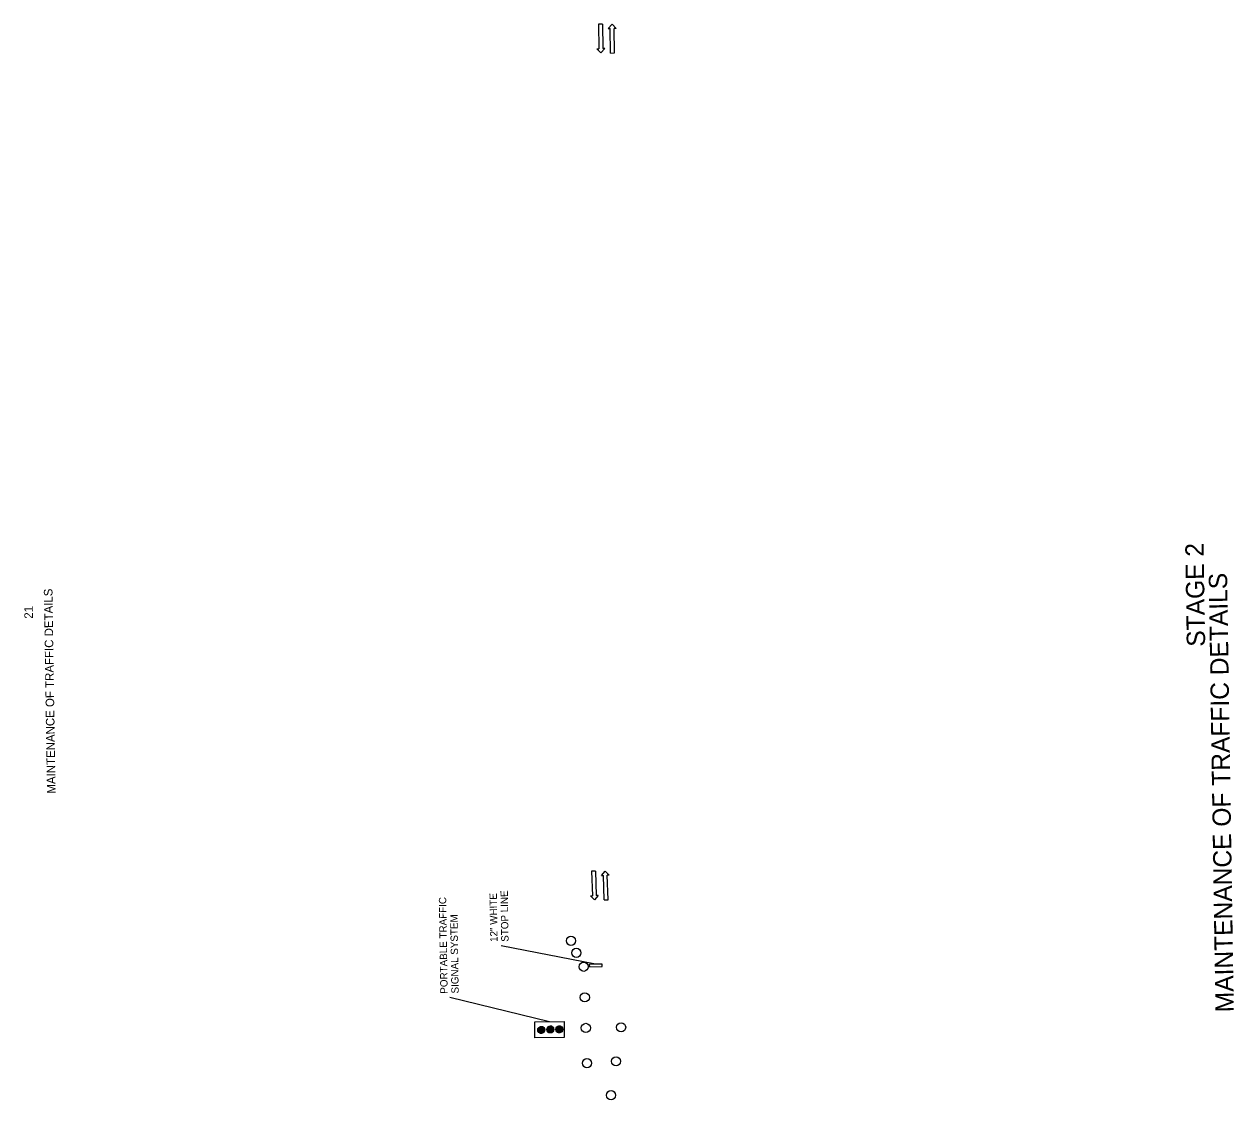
# Model space of a CAD drawing. Extents: x 1770139 to 1773492, y 718230 to 727190.
# Drawn here: x 1770334 to 1771322, y 725184 to 726062 of the extents above; entities that cross this region are included whole.
import ezdxf

# ---------------------------------------------------------------- set-up
doc = ezdxf.new("R2010")
doc.units = 0
for name, color, linetype in [('Default', 7, 'Continuous'), ('R_Border', 7, 'Continuous'), ('R_Border Notes', 7, 'Continuous'), ('R_Dimension', 7, 'Continuous'), ('R_MOT', 7, 'Continuous')]:
    doc.layers.add(name, color=color, linetype=linetype)

msp = doc.modelspace()

# ---------------------------------------------------------------- linework, layer by layer
at = {"layer": 'Default'}
for p, q in [((1770795.47, 725294.29), (1770795.54, 725292.29)), ((1770795.54, 725292.29), (1770806.07, 725292.65)), ((1770806.07, 725292.65), (1770806.01, 725294.64)), ((1770756.38, 725237.94), (1770753.33, 725240.9)), ((1770756.21, 725237.94), (1770753.33, 725240.73)), ((1770756.55, 725237.96), (1770753.34, 725241.06)), ((1770756.02, 725237.94), (1770753.35, 725240.54)), ((1770756.7, 725237.98), (1770753.36, 725241.22)), ((1770755.82, 725237.96), (1770753.37, 725240.34)), ((1770756.85, 725238.01), (1770753.39, 725241.37)), ((1770756.99, 725238.05), (1770753.42, 725241.51)), ((1770755.61, 725238), (1770753.42, 725240.12)), ((1770757.13, 725238.09), (1770753.46, 725241.65)), ((1770755.36, 725238.06), (1770753.49, 725239.88)), ((1770757.26, 725238.14), (1770753.5, 725241.78)), ((1770757.39, 725238.19), (1770753.55, 725241.91)), ((1770757.51, 725238.25), (1770753.6, 725242.03)), ((1770757.62, 725238.31), (1770753.66, 725242.15)), ((1770757.73, 725238.38), (1770753.73, 725242.26)), ((1770757.84, 725238.45), (1770753.79, 725242.37)), ((1770757.94, 725238.52), (1770753.86, 725242.48)), ((1770758.04, 725238.6), (1770753.94, 725242.58)), ((1770758.14, 725238.68), (1770754.02, 725242.67)), ((1770758.23, 725238.77), (1770754.1, 725242.77)), ((1770758.31, 725238.86), (1770754.19, 725242.86)), ((1770758.4, 725238.95), (1770754.28, 725242.94)), ((1770758.48, 725239.05), (1770754.37, 725243.03)), ((1770758.55, 725239.15), (1770754.47, 725243.1)), ((1770758.62, 725239.25), (1770754.58, 725243.18)), ((1770758.69, 725239.36), (1770754.68, 725243.25)), ((1770758.75, 725239.48), (1770754.79, 725243.32)), ((1770758.81, 725239.59), (1770754.91, 725243.38)), ((1770758.87, 725239.72), (1770755.03, 725243.43)), ((1770758.91, 725239.84), (1770755.16, 725243.49)), ((1770758.96, 725239.97), (1770755.29, 725243.53)), ((1770759, 725240.11), (1770755.42, 725243.58)), ((1770759.03, 725240.25), (1770755.56, 725243.61)), ((1770759.05, 725240.4), (1770755.71, 725243.64)), ((1770759.07, 725240.56), (1770755.87, 725243.67)), ((1770759.08, 725240.73), (1770756.03, 725243.68)), ((1770759.08, 725240.9), (1770756.21, 725243.69)), ((1770759.07, 725241.08), (1770756.39, 725243.68)), ((1770759.04, 725241.28), (1770756.59, 725243.66)), ((1770759, 725241.5), (1770756.81, 725243.62)), ((1770758.93, 725241.75), (1770757.06, 725243.56)), ((1770758.81, 725242.03), (1770757.35, 725243.45)), ((1770758.59, 725242.42), (1770757.74, 725243.24)), ((1770763.86, 725238.32), (1770760.81, 725241.28)), ((1770763.69, 725238.32), (1770760.81, 725241.1)), ((1770764.03, 725238.34), (1770760.82, 725241.44)), ((1770763.51, 725238.32), (1770760.83, 725240.92)), ((1770764.18, 725238.36), (1770760.84, 725241.6)), ((1770763.31, 725238.34), (1770760.85, 725240.72)), ((1770764.33, 725238.39), (1770760.87, 725241.75)), ((1770764.48, 725238.43), (1770760.9, 725241.89)), ((1770763.09, 725238.38), (1770760.9, 725240.5)), ((1770764.61, 725238.47), (1770760.94, 725242.03)), ((1770762.84, 725238.44), (1770760.97, 725240.26)), ((1770764.74, 725238.52), (1770760.98, 725242.16)), ((1770764.87, 725238.57), (1770761.03, 725242.29)), ((1770764.99, 725238.63), (1770761.08, 725242.41)), ((1770762.55, 725238.55), (1770761.08, 725239.97)), ((1770765.1, 725238.69), (1770761.14, 725242.53)), ((1770765.21, 725238.75), (1770761.21, 725242.64)), ((1770765.32, 725238.82), (1770761.27, 725242.75)), ((1770765.42, 725238.9), (1770761.34, 725242.85)), ((1770765.52, 725238.98), (1770761.42, 725242.96)), ((1770765.62, 725239.06), (1770761.5, 725243.05)), ((1770765.71, 725239.15), (1770761.58, 725243.15)), ((1770765.8, 725239.23), (1770761.67, 725243.24)), ((1770765.88, 725239.33), (1770761.76, 725243.32)), ((1770765.96, 725239.43), (1770761.85, 725243.4)), ((1770766.03, 725239.53), (1770761.95, 725243.48)), ((1770766.1, 725239.63), (1770762.06, 725243.56)), ((1770766.17, 725239.74), (1770762.16, 725243.63)), ((1770766.23, 725239.85), (1770762.27, 725243.69)), ((1770766.29, 725239.97), (1770762.39, 725243.76)), ((1770766.35, 725240.09), (1770762.51, 725243.81)), ((1770766.39, 725240.22), (1770762.64, 725243.87)), ((1770766.44, 725240.35), (1770762.77, 725243.91)), ((1770766.48, 725240.49), (1770762.9, 725243.96)), ((1770766.51, 725240.63), (1770763.04, 725243.99)), ((1770766.53, 725240.78), (1770763.19, 725244.02)), ((1770766.55, 725240.94), (1770763.35, 725244.05)), ((1770766.56, 725241.1), (1770763.51, 725244.06)), ((1770766.56, 725241.28), (1770763.69, 725244.07)), ((1770766.55, 725241.46), (1770763.87, 725244.06)), ((1770766.52, 725241.66), (1770764.07, 725244.04)), ((1770766.48, 725241.88), (1770764.29, 725244)), ((1770766.41, 725242.12), (1770764.54, 725243.94)), ((1770766.29, 725242.41), (1770764.83, 725243.83)), ((1770766.07, 725242.8), (1770765.22, 725243.62)), ((1770771.04, 725238.43), (1770768.08, 725241.29)), ((1770771.21, 725238.44), (1770768.09, 725241.46)), ((1770770.86, 725238.43), (1770768.09, 725241.11)), ((1770771.37, 725238.46), (1770768.1, 725241.63)), ((1770770.66, 725238.44), (1770768.11, 725240.92)), ((1770771.52, 725238.48), (1770768.12, 725241.78)), ((1770770.45, 725238.47), (1770768.14, 725240.71)), ((1770771.67, 725238.52), (1770768.15, 725241.93)), ((1770771.81, 725238.56), (1770768.19, 725242.07)), ((1770770.22, 725238.52), (1770768.2, 725240.48)), ((1770771.94, 725238.6), (1770768.23, 725242.2)), ((1770772.07, 725238.65), (1770768.27, 725242.33)), ((1770769.96, 725238.61), (1770768.29, 725240.22)), ((1770772.19, 725238.71), (1770768.32, 725242.45)), ((1770772.31, 725238.76), (1770768.38, 725242.57)), ((1770772.42, 725238.83), (1770768.44, 725242.69)), ((1770769.62, 725238.76), (1770768.45, 725239.89)), ((1770772.53, 725238.9), (1770768.5, 725242.8)), ((1770772.64, 725238.97), (1770768.57, 725242.91)), ((1770772.74, 725239.04), (1770768.65, 725243.01)), ((1770772.83, 725239.12), (1770768.72, 725243.11)), ((1770772.93, 725239.21), (1770768.8, 725243.21)), ((1770773.02, 725239.3), (1770768.89, 725243.3)), ((1770773.1, 725239.39), (1770768.98, 725243.39)), ((1770773.18, 725239.48), (1770769.07, 725243.47)), ((1770773.26, 725239.58), (1770769.17, 725243.55)), ((1770773.33, 725239.68), (1770769.27, 725243.63)), ((1770773.4, 725239.79), (1770769.37, 725243.7)), ((1770773.47, 725239.9), (1770769.48, 725243.77)), ((1770773.53, 725240.02), (1770769.59, 725243.83)), ((1770773.59, 725240.14), (1770769.71, 725243.89)), ((1770773.68, 725240.39), (1770769.96, 725244)), ((1770773.72, 725240.52), (1770770.09, 725244.04)), ((1770773.76, 725240.66), (1770770.23, 725244.08)), ((1770773.79, 725240.81), (1770770.38, 725244.12)), ((1770773.81, 725240.96), (1770770.53, 725244.15)), ((1770773.83, 725241.12), (1770770.69, 725244.16)), ((1770773.83, 725241.29), (1770770.86, 725244.18)), ((1770773.83, 725241.47), (1770771.04, 725244.18)), ((1770773.81, 725241.66), (1770771.23, 725244.16)), ((1770773.78, 725241.87), (1770771.44, 725244.14)), ((1770773.72, 725242.1), (1770771.67, 725244.09)), ((1770773.63, 725242.36), (1770771.93, 725244.01)), ((1770755.07, 725238.17), (1770753.6, 725239.59)), ((1770754.68, 725238.38), (1770753.82, 725239.21)), ((1770762.16, 725238.76), (1770761.3, 725239.59))]:
    msp.add_line(p, q, dxfattribs=at)
msp.add_lwpolyline([(1770806.01, 725294.64), (1770800.6, 725294.46), (1770795.47, 725294.29)], dxfattribs=at)
msp.add_lwpolyline([(1770751.08, 725234.31), (1770750.88, 725247.3), (1770774.85, 725247.66), (1770775.05, 725234.68)], close=True, dxfattribs=at)
for centre in [(1770756.21, 725240.81), (1770763.69, 725241.19), (1770770.96, 725241.3)]:
    msp.add_circle(centre, 2.87, dxfattribs=at)
at = {"layer": 'R_Border Notes'}
for p, q in [((1770806.14, 726062.1), (1770802.94, 726062.05)), ((1770802.94, 726062.05), (1770803.25, 726042.07)), ((1770806.14, 726062.1), (1770806.45, 726042.12)), ((1770810.89, 726058.5), (1770814.04, 726062.06)), ((1770814.04, 726062.06), (1770817.29, 726058.6)), ((1770810.89, 726058.5), (1770812.49, 726058.53)), ((1770812.8, 726038.55), (1770812.49, 726058.53)), ((1770817.29, 726058.6), (1770815.69, 726058.58)), ((1770816, 726038.59), (1770815.69, 726058.58)), ((1770801.65, 726042.05), (1770803.25, 726042.07)), ((1770804.9, 726038.59), (1770801.65, 726042.05)), ((1770808.05, 726042.15), (1770804.9, 726038.59)), ((1770808.05, 726042.15), (1770806.45, 726042.12)), ((1770812.8, 726038.55), (1770816, 726038.59)), ((1770800.49, 725370.5), (1770797.29, 725370.4)), ((1770797.29, 725370.4), (1770797.93, 725350.42)), ((1770800.49, 725370.5), (1770801.13, 725350.53)), ((1770805.3, 725366.98), (1770808.38, 725370.59)), ((1770808.38, 725370.59), (1770811.69, 725367.18)), ((1770805.3, 725366.98), (1770806.9, 725367.03)), ((1770807.54, 725347.06), (1770806.9, 725367.03)), ((1770811.69, 725367.18), (1770810.1, 725367.13)), ((1770810.73, 725347.16), (1770810.1, 725367.13)), ((1770796.33, 725350.37), (1770797.93, 725350.42)), ((1770799.64, 725346.97), (1770796.33, 725350.37)), ((1770802.73, 725350.58), (1770799.64, 725346.97)), ((1770802.73, 725350.58), (1770801.13, 725350.53)), ((1770807.54, 725347.06), (1770810.73, 725347.16))]:
    msp.add_line(p, q, dxfattribs=at)
at = {"layer": 'R_Dimension'}
for p, q in [((1770800.6, 725294.46), (1770723.51, 725309.6)), ((1770762.86, 725247.48), (1770681.72, 725267.3))]:
    msp.add_line(p, q, dxfattribs=at)
at = {"layer": 'R_MOT'}
for centre in [(1770780.47, 725313.61), (1770784.86, 725303.75), (1770790.88, 725292.41), (1770791.75, 725267.43), (1770792.63, 725242.45), (1770821.4, 725242.95), (1770793.52, 725213.65), (1770817.29, 725215.22), (1770813.18, 725187.49)]:
    msp.add_circle(centre, 3.75, dxfattribs=at)

# ---------------------------------------------------------------- texts
at = {"layer": 'Default'}
for s, p in [('STAGE 2', (1771298.16, 725553.85)), ('MAINTENANCE OF TRAFFIC DETAILS', (1771321.54, 725255.35))]:
    msp.add_text(s, height=15, rotation=90.88269, dxfattribs=at).set_placement(p)
at = {"layer": 'R_Border'}
for s, p in [('MAINTENANCE OF TRAFFIC DETAILS', (1770359.81, 725433.81)), ('21', (1770341.34, 725576.67))]:
    msp.add_text(s, height=7, rotation=90.88269, dxfattribs=at).set_placement(p)
at = {"layer": 'R_Dimension'}
for s, p in [('PORTABLE TRAFFIC', (1770679.86, 725270.48)), ('12" WHITE', (1770720.58, 725312.72)), ('STOP LINE', (1770729.58, 725312.86)), ('SIGNAL SYSTEM', (1770688.86, 725270.62))]:
    msp.add_text(s, height=6, rotation=90.88269, dxfattribs=at).set_placement(p)

doc.saveas('drawing.dxf')
